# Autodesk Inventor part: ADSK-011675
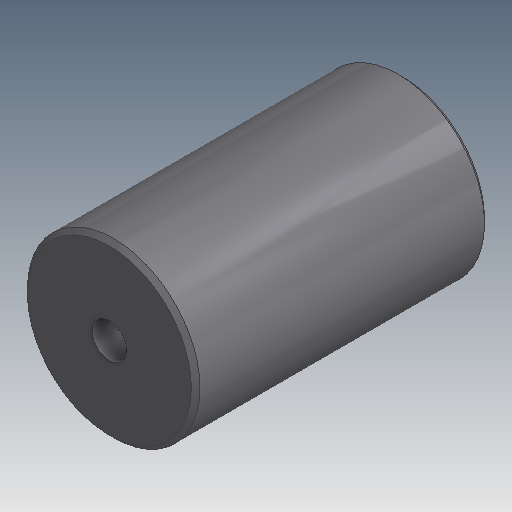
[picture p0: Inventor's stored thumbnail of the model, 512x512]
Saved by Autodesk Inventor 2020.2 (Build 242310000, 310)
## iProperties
Created: 2000-02
Part Number: ADSK-011675
Description: SHFTTA,RC,AX,035,12,XD,MNT,BUMPER
Document SubType Name: Modeling
Designer: sgadau
Material: Acier doux
Density: 7.86 g/cm^3
Appearance: Metal-Steel(Polish)
Mass: 319.772 g
Surface Area: 79.8524 cm^2
Volume: 40.6835 cm^3
Control State: 0
Master: False
Checked Out: False
Shininess: 60.0
Length Units: 11272
Angle Units: 11279
Time Units: 11290
Mass Units: 11286
Length Display Precision: 3
Angle Display Precision: 2
Compacted: True
Cutlength: 2.38
Material Desc: ROUND,CD 1018,1.2500 DIA
Material_Number: A084566
Dimensions: 1,3x2,1x1,2 in
Mass: 0,705 lb
VLT_Material: Acier doux
Density: 7.86
Volumn: 60.32985923004582
Area: 91.84073058642146
PropertySet Name: Model Information
Title: 500625
Author: sgadau
Revision Number: -
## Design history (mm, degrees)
node "Extrusion1" dims "d1" = 53.975, "d2" = 0
node "Hole1" dims "d3" = 7.7978, "d4" = 9.525, "d5" = 6.35, "d6" = 60 deg, "d7" = 19.05, "d8" = 118 deg
node "Hole2" dims "d9" = 6.4008, "d10" = 9.525, "d11" = 6.35, "d12" = 60 deg, "d13" = 31.75, "d14" = 118 deg
node "Chamfer1" dims "d15" = 0.79375, "d16" = 0.79375, "d17" = 45 deg
node "Solide1"
node "Corps solides"
node "Corps surfaciques"
sketch "Sketch1"
  geometry: C1 r 15.875 at (-48.636, 110.022)
  constraints: 1 centre point, 1 other
  dimensions: "d0" = 31.75 diameter of C1
sketch "Sketch2"
  geometry: C1 r 15.875 at (0, 0) reference; 1 further point
  constraints: 1 coincident
sketch "Sketch3"
  geometry: C1 r 15.875 at (0, 0) reference; 1 further point
  constraints: 1 coincident
